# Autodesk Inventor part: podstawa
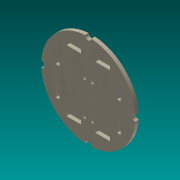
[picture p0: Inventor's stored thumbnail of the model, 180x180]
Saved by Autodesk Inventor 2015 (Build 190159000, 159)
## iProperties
Created: 2016-02
Part Number: podstawa
Material: Generic
Document SubType Name: Modeling
Designer: Rafał
Density: 1 g/cm^3
Appearance: Light Beige
Author: Rafał
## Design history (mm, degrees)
sketch "Sketch1"
  geometry: C1 r 65 at (0, 0); 1 further point
  constraints: 1 centre point, 1 coincident
  dimensions: "d0" = 130 diameter of C1
extrude "Extrusion1" new body sketch "Sketch1" distance "d1" = 5; taper "d2" = 0 deg
sketch "Sketch2" dims "d3" = 90, "d10" = 130
  geometry: L1 (45, 45)-(45, -45); L2 (45, -45)-(-45, -45); L3 (-45, -45)-(-45, 45); L4 (-45, 45)-(45, 45); L5 (-45, 0)-(-45, 10); L6 (-45, 10)-(-40, 10); L7 (-40, 10)-(-40, 30); L8 (-40, 30)-(-45, 30); L9 (-45, 30)-(-45, 10); L10 (0, 45)-(-10, 45); L11 (-45, 0)-(0, 0); L12 (0, 0)-(0, 45); L13 (-10, 45)-(-30, 45); L14 (-30, 45)-(-30, 40); L15 (-30, 40)-(-10, 40); L16 (-10, 40)-(-10, 45); L17 (-40, -10)-(-40, -30); L18 (-40, -30)-(-45, -30); L19 (-45, -30)-(-45, -10); L20 (-45, -10)-(-40, -10); L21 (-30, -45)-(-30, -40); L22 (-10, -45)-(-30, -45); L23 (-10, -40)-(-10, -45); L24 (-30, -40)-(-10, -40); L25 (10, 40)-(10, 45); L26 (10, 45)-(30, 45); L27 (30, 45)-(30, 40); L28 (30, 40)-(10, 40); L29 (40, 30)-(45, 30); L30 (40, 10)-(40, 30); L31 (45, 30)-(45, 10); L32 (45, 10)-(40, 10); L33 (40, -30)-(45, -30); L34 (40, -10)-(40, -30); L35 (45, -10)-(40, -10); L36 (30, -40)-(10, -40); L37 (30, -45)-(30, -40); L38 (10, -40)-(10, -45); L39 (-45, 0)-(-68.355, 0); L40 (10, -40)-(30, -40); L41 (30, -40)-(30, -45); L42 (30, -45)-(10, -45); L43 (10, -45)-(10, -40); L44 (45, -30)-(40, -30); L45 (40, -30)-(40, -10); L46 (40, -10)-(45, -10); L47 (45, -10)-(45, -30); L48 (0, 0)-(0, -12.9); L49 (0, -12.9)-(5.4, -12.9); L50 (0, 0)-(0, 33.9); L51 (0, 33.9)-(5.4, 33.9); C1 r 4.25 at (-65, 0); C2 r 4.25 at (0, -65); C3 r 4.25 at (65, 0); C4 r 4.25 at (0, 65); C5 r 2 at (5.4, -12.9); C6 r 2 at (5.4, 33.9); C7 r 2 at (-5.4, 33.9); C8 r 2 at (-5.4, -12.9); 4 further points
  constraints: 102 end point, 28 symmetric about line, 8 centre point, 8 parallel, 7 coincident, 6 horizontal, 6 perpendicular, 4 point on line, 2 midpoint, 1 horizontal alignment, 1 vertical, 1 vertical alignment, 24 other
  dimensions: "d4" = 10 distance of L5.start L5.end; "d5" = 5 distance of L8.end L7.end; "d6" = 20 distance of L7.end L6.end; "d7" = 10 distance of L10.start L10.end; "d8" = 20 distance of L15.end L14.end; "d9" = 5 distance of L14.end L13.end; "d11" = 8.5 diameter of C1; "d14" = 360 deg dimension on point (0, 0) C1.centre (derived); "d16" = 12.9 distance of L48.start L48.end; "d17" = 5.4 distance of L48.end L49.end; "d18" = 4 diameter of C5; "d19" = 33.9 distance of L48.start L50.end; "d20" = 4 diameter of C6
extrude "Extrusion2" cut sketch "Sketch2" distance "d21" = 10; taper "d22" = 0 deg
body "Solid1"
